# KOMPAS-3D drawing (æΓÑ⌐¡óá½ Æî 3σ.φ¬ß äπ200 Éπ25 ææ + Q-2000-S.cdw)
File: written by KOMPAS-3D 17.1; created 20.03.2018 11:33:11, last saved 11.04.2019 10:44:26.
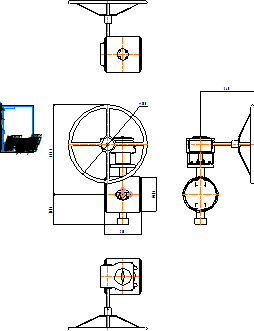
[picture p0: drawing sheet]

Sheet 1: A4, portrait

Title block, sheet 1: name: Стейнвал ТМ 3х.экс / Ду200 Ру25 СС + Q-2000-S; material: Внимание! Данный продукт является объектом авторского права ООО «Торговый Дом АДЛ». / Запрещается изменение, копирование, распространение / (в том числе путем копирования на другие сайты и ресурсы в Интернете) / или любое иное использование информации и объектов без предварительного / согласия правообладателя (ООО «Торговый Дом АДЛ»).; mass: 97,3; sheets: 1; organisation: ООО "Торговый дом АДЛ"; sheet format: A4; stored path: \\adlc.lan\data\АДЛ_ПКД\3D-модели\ADL production\Дисковые поворотные затворы СТЕЙНВАЛ\Трехэксцентриковый\Стейнвал c-c\С редуктором\KOMPAS 2D\Стейнвал ТМ 3х.экс Ду200 Ру25 СС + Q-2000-S.cdw

Views: Вид 1, Проекционный вид 2, Проекционный вид 3, Проекционный вид 4
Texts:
  kka
  adl
Dimensions and other numbers on the sheet: 500; 230; 219; 191,8; 569,5; 340; 1:1; 1; 97,3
